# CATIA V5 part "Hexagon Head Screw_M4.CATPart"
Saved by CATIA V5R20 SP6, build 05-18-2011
Part number: Hexagon_Head_Screw_M4
Bounding box of the stored display mesh (mm): x -3.681 to 3.681, y -3.681 to 3.681, z -28 to 0
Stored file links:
  E:\#01 CATIA Lecture Materials\#06 DMU\#03 DMU Page01 KIN EX03\Hexagon Head Screw_M4.CATPart
  F:\RCCAR\Project(MJ)\hexagon head screw.xls
  C:\Program Files\Dassault Systemes\B20\win_b64\startup\materials\Catalog.CATMaterial
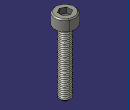
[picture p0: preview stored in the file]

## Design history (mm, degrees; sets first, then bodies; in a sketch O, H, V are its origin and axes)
External parameters (linked from other documents)
  External.d_Head = 7.38 mm
  External.K_Head_Height = 4 mm
  External.ds_Body = 4 mm
  External.Pitch = 0.6 mm
  External.lead = 24 mm
  External.v = 0.4 mm
  External.k = 0.95 mm
  External.t = 2 mm
  External.s = 3.575 mm
  `External.Bolt Type` = "M4"
Body1 (main body)
  Body2
    Sketch1 on yz-plane, origin (0, 0, 0), H (0, 1, 0), V (0, 0, 1)
      line L1 (3.69, -4) -> (3.69, 0)
      point P2 (3.69, 0)
      line L2 (3.69, 0) -> (0, 0)
      construction line L3 (0, 50.6222) -> (0, -71.272)
      point P3 (0, 50.6222)
      line L4 (3.69, -4) -> (0, -4)
      point P5 (0, -4)
      axis line L5 (0, 17.6953) -> (0, -27.6198)
      point P6 (0, 17.6953)
      reference intersected line E1 through (0, -4) direction (-1, 0) from Plane1
      distance L1 L3 = 3.69 {= External.d_Head /2}
      coincidence: P2 H, P3 V, P6 L3, E1 L4, P5 V
      vertical: L1 V, L3 V, L5 V
      horizontal: L2 H, L4 H
    Shaft1: profile Sketch1, axis Sketch1.L5, angle 360
    Chamfer1: length 0.4 {= External.v}, angle 45, on edge [face of Shaft1 from Sketch1.L2 | face of Shaft1 from Sketch1.L1]
    Body3
      Sketch2 on face of Shaft1 from Sketch1.L4, origin (0, 0, -4), H (1, 0, 0), V (0, -1, 0)
        circle A1 centre (0, 0) radius 2
        radius A1 = 2 {= External.ds_Body /2}
      Pad1: profile Sketch2, direction (0, 0, -1), length 24 {= External.lead}
      Chamfer2: length 0.95 {= External.k}, angle 45, on edge [face of Pad1 from Sketch2.A1 | end face of Pad1]
      Split1: SplitPlane Join1
    Assemble1: tool Body3
  Assemble2: tool Body2
  Body4
    Sketch3 on xy-plane, origin (0, 0, 0), H (1, 0, 0), V (0, 1, 0)
      point P1 (0, 0)
      point P2 (1.7875, -1.032)
      point P3 (1.7875, 1.032)
      point P4 (0, 2.064)
      point P5 (-1.7875, 1.032)
      point P6 (-1.7875, -1.032)
      point P7 (0, -2.064)
      point P8 (1.7875, 0)
      line L1 (1.7875, -1.032) -> (1.7875, 1.032)
      line L2 (1.7875, 1.032) -> (0, 2.064)
      line L3 (0, 2.064) -> (-1.7875, 1.032)
      line L4 (-1.7875, 1.032) -> (-1.7875, -1.032)
      line L5 (-1.7875, -1.032) -> (0, -2.064)
      line L6 (0, -2.064) -> (1.7875, -1.032)
      construction line L7 (0, 0) -> (1.7875, 0)
      construction circle A1 centre (0, 0) radius 2.064
      construction arc A2 centre (-1.7875, -1.032) radius 2.064 from (-1.7875, 1.032) to (0, -2.064) cw
      construction arc A3 centre (1.7875, 1.032) radius 2.064 from (0, 2.064) to (1.7875, -1.032) ccw
      distance L1 L4 = 3.575 {= External.s}
      coincidence: P1 V, A1 P2, A1 P3, A1 P4, A1 P5, A1 P6, A1 P7, A2 P1, A3 P1, H L7
      horizontal: L7 H
      midpoint: P8 L1
    Pocket1: profile Sketch3, direction (0, 0, -1), length 2 {= External.t}
    Set1 "Reference Data"
      Point1 "Center Point": (0, 0, 0)
      Plane1: type Offset, RefPlane xy-plane, Offset 4 {= External.K_Head_Height}, reversed
      Set2 "Helix Body"
        Helix1: Direction Z axis, RefPoint {point type Coord, X 0, Y 2 {= External.ds_Body /2}, Z -3 {= -External.K_Head_Height +1mm}}, Pitch 0.6 {= External.Pitch}, Height 34 {= External.lead +10mm}, TaperAngle 0
        Sweep1: type Segment, GuideCrv Helix1, Length1 0.6 {= External.Pitch}, Length2 0.2, Angle 60, DraftDirection xy-plane
        Sweep2: type Segment, GuideCrv Helix1, Length1 0.6 {= External.Pitch}, Length2 0.2, Angle 60, DraftDirection xy-plane
        Trim1: Trimmed (Sweep1; Sweep2)
        Split2: ToCut Trim1, Cutting Plane1
        Fill1: Boundary {boundary Boundary edge of Split2, Support Split2}
        Join1: Elements (Split2; Fill1)
  Remove1: tool Body4
Relations
  rule:
    if `External.Bolt Type` =="M1.6"
    	{
    		External.d_Head =3.14mm
    		External.K_Head_Height =1.6mm
    		External.ds_Body =1.6mm
    		External.Pitch =0.35mm
    		External.lead =10mm
    		External.v=0.16mm
    		External.k =0.16mm
    		External.t =0.7mm
    		External.s =1.545mm
    	}
    else if `External.Bolt Type` =="M2"
    	{
    		External.d_Head =3.98mm
    		External.K_Head_Height =2mm
    		External.ds_Body =2mm
    		External.Pitch =0.4mm
    		External.lead =10mm
    		External.v=0.2mm
    		External.k =0.25mm
    		External.t =1mm
    		External.s =1.545mm
    	}
    else if `External.Bolt Type` =="M2.5"
    	{
    		External.d_Head =4.68mm
    		External.K_Head_Height =2.5mm
    		External.ds_Body =2.5mm
    		External.Pitch =0.45mm
    		External.lead =10mm
    		External.v=0.25mm
    		External.k =0.4mm
    		External.t =1.1mm
    		External.s=2.045mm
    	}
    else if `External.Bolt Type` =="M3"
    	{
    		External.d_Head =5.5mm
    		External.K_Head_Height =3mm
    		External.ds_Body =3mm
    		External.Pitch =0.5mm
    		External.lead =10mm
    		External.v=0.3mm
    		External.k =0.6mm
    		External.t =1.3mm
    		External.s=2.56mm
    	}
    else if `External.Bolt Type` =="M3.5"
    	{
    		External.d_Head =6.38mm
    		External.K_Head_Height =3.5mm
    		External.ds_Body =3.5mm
    		External.Pitch =0.55mm
    		External.lead =15mm
    		External.v=0.35mm
    		External.k =0.75mm
    		External.t =1.5mm
    		External.s=3.06mm
    	}
    else if `External.Bolt Type` =="M4"
    	{
    		External.d_Head =7.38mm
    		External.K_Head_Height =4mm
    		External.ds_Body =4mm
    		External.Pitch =0.6mm
    		External.lead =24mm
    		External.v=0.4mm
    		External.k =0.95mm
    		External.t =2mm
    		External.s=3.575mm
    	}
